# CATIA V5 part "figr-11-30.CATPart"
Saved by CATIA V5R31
Part number: Part1
Bounding box of the stored display mesh (mm): x -205 to 53, y -75.374 to 75.374, z 0 to 37.54
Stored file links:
  D:\PROJECTS\Project 2021\US EDITION\CATIA V5 6R 2021\Resources\Part Files\c11_catia_v5_6r2021_prt\figr-11-30.CATPart
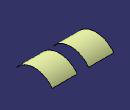
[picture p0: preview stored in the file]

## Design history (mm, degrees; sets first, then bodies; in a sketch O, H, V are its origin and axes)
Set1
  Extrude1: Element1 Sketch1, Lim1 53, Lim2 52, Direction yz-plane
  Translate1: ToTransfor Extrude1, Direction edge of Extrude1, Length 153
Body1 (main body)
  Sketch1 on yz-plane, origin (0, 0, 0), H (0, 1, 0), V (0, 0, 1)
    arc A1 centre (0, -56.4477) radius 94.1675 from (-75.3736, 0) to (75.3736, 0) cw
    point P1 (0, -56.4477)
    point P2 (-75.3736, 0)
    point P3 (75.3736, 0)
    point P4 (0, 37.7198)
    coincidence: P2 H, P3 H, A1 P4, P4 V, P1 V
